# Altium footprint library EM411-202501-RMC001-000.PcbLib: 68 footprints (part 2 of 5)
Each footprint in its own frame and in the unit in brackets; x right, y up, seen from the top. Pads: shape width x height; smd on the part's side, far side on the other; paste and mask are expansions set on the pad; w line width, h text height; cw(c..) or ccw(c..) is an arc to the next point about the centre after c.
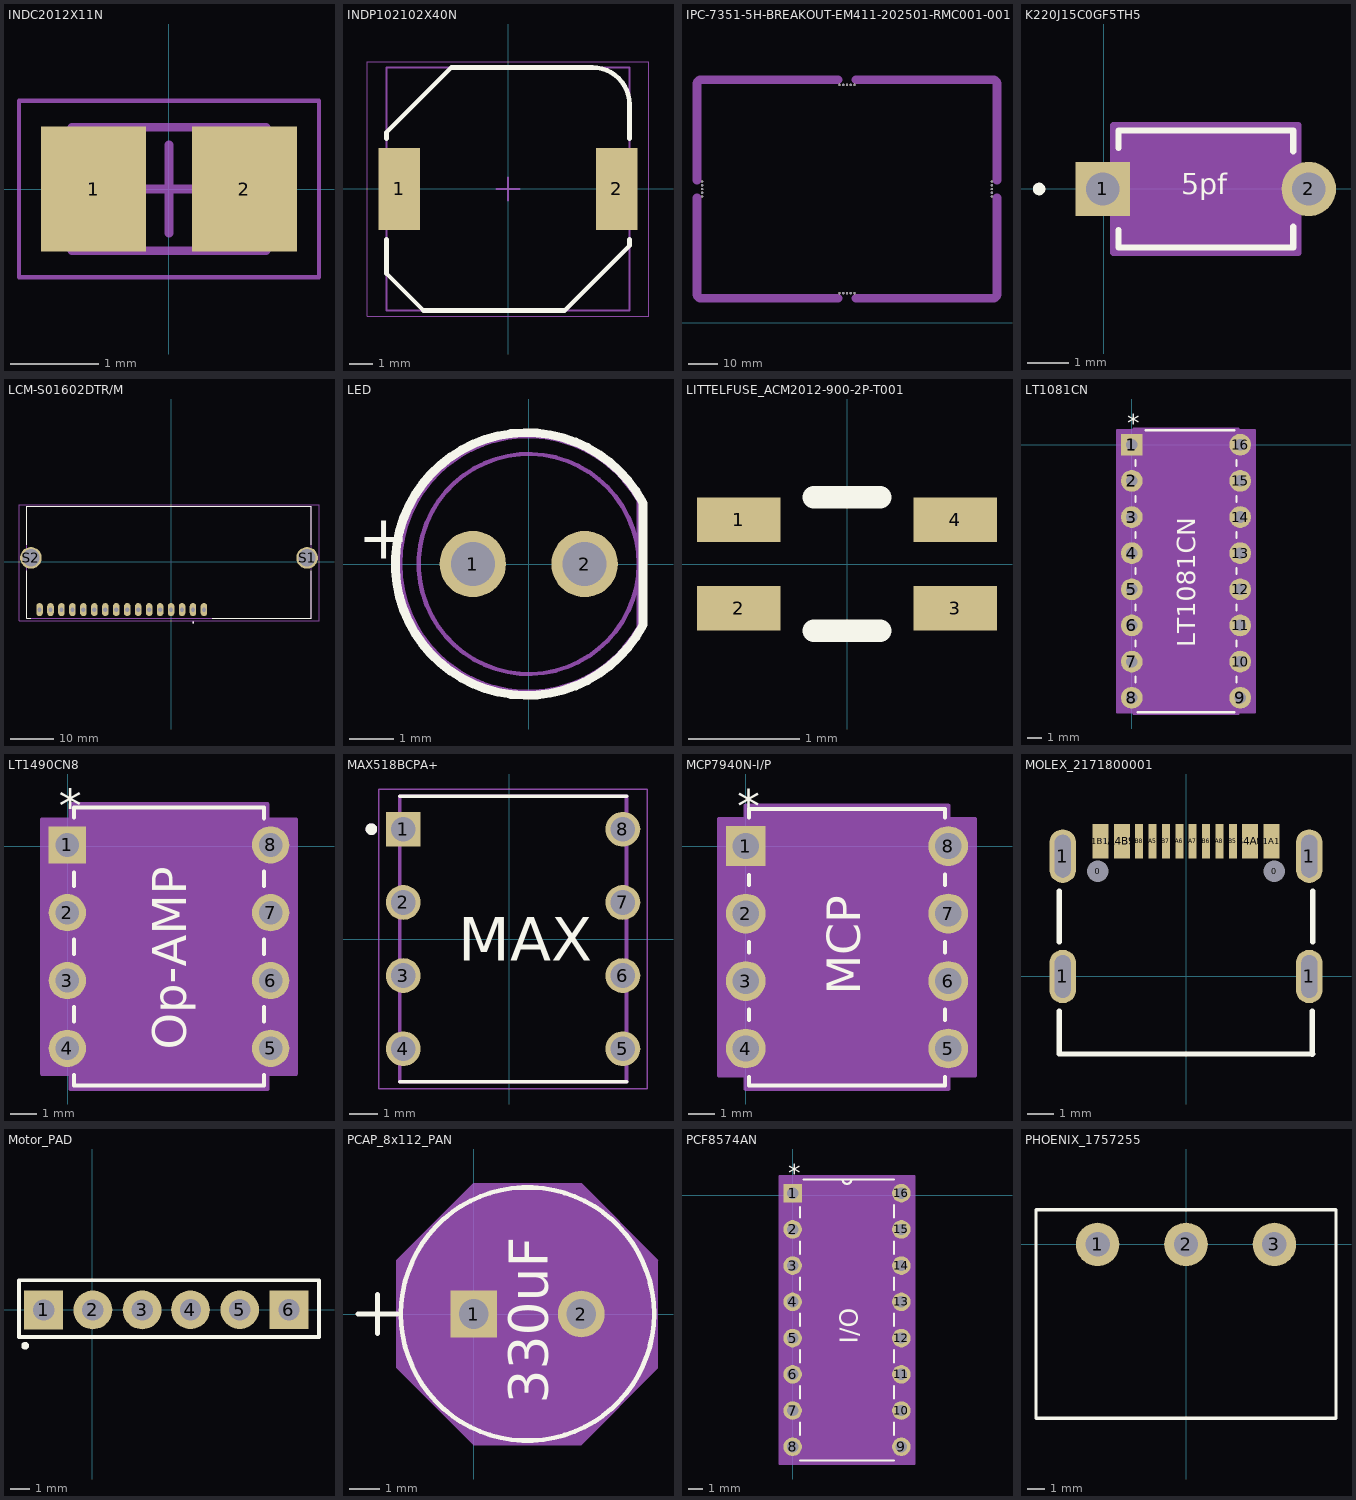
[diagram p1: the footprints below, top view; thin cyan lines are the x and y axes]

## INDC2012X11N [mm] "Chip Inductor, 2-Leads, Body 2.00x1.20mm, IPC Medium Density"
height 1.1
pads (2):
  rect 1.19x1.42 smd: 1(-0.855,0) 2(0.855,0)
Mechanical 13:
  lines w0.1: -1.1,-0.7 1.1,-0.7 1.1,0.7 -1.1,0.7 -1.1,-0.7
Mechanical 15:
  lines w0.05: -1.7,-1 1.7,-1 1.7,1 -1.7,1 -1.7,-1
  lines w0.1: -0.5,0 0.5,0 ; 0,-0.5 0,0.5
3D body "INDC2012X11N.step": height 1.1, standoff 0, extent -1.1,-0.7 1.1,0.7

## INDP102102X40N [mm] "Precision Wire Wound Inductor, 2-Leads, Body 10.20x10.15mm, IPC Medium Density"
height 4
pads (2):
  rect 1.78x3.56 smd: 1(-4.7,0) 2(4.7,0)
Top Overlay:
  lines w0.2: -5.25,-2.18 -5.25,-3.65 -3.65,-5.25 2.45,-5.25 5.25,-2.45 5.25,-2.18 ; -5.25,2.18 -5.25,2.45 -2.45,5.25 3.65,5.25 cw(c3.65,3.65) 5.25,3.65 5.25,2.18
Top Courtyard:
  lines w0.05: -6.075,-5.5 -6.075,5.5 6.075,5.5 6.075,-5.5 -6.075,-5.5
  lines w0.1: -0.5,0 0.5,0 ; 0,-0.5 0,0.5
Mechanical 13:
  lines w0.1: -5.25,-5.25 -5.25,5.25 5.25,5.25 5.25,-5.25 -5.25,-5.25
3D body "Coilcraft-MSS1038.STEP": height 3.6, standoff -0.4, extent -5.15,-5.1 5.15,5.1

## IPC-7351-5H-BREAKOUT-EM411-202501-RMC001-001 [mil] "IPC-7351 Breakout for EM411-202401-RMC001-001"
pads (20):
  round 31 hole 31 unplated: 0(403.7,1711.02) 0(403.7,1761.02) 0(403.7,1811.02) 0(403.7,1861.02) 0(403.7,1911.02) 0(2262.2,403.7) 0(2262.2,3218.35) 0(2312.2,403.7) 0(2312.2,3218.35) 0(2362.2,403.7) 0(2362.2,3218.35) 0(2412.2,403.7) 0(2412.2,3218.35) 0(2462.2,403.7) 0(2462.2,3218.35) 0(4320.71,1711.02) 0(4320.71,1761.02) 0(4320.71,1811.02) 0(4320.71,1861.02) 0(4320.71,1911.02)
Route Tool Path:
  lines w118.11: 334.64,1692.91 334.64,393.7 ccw(c393.7,393.7) 393.7,334.64 2244.09,334.65 ; 334.65,1929.13 334.65,3228.35 cw(c393.7,3228.35) 393.7,3287.4 2244.09,3287.4 ; 2480.31,334.65 4330.71,334.64 ccw(c4330.71,393.7) 4389.76,393.7 4389.76,1692.91 ; 2480.31,3287.4 4330.71,3287.4 cw(c4330.71,3228.35) 4389.76,3228.35 4389.76,1929.13

## K220J15C0GF5TH5 [mil]
pads (2):
  rect 52x52 hole 32 paste-99999 mask+0: 1(-0.55,-0.19)
  round 52 hole 32 paste-99999 mask+0: 2(196.3,-0.19)
Top Overlay:
  circle w6: c-61.55,-0.19 r3
  lines w6: 14.38,-39.29 14.38,-56.19 181.38,-56.19 181.38,-36.33 ; 14.38,38.91 14.38,55.81 181.38,55.81 181.38,35.95
  text "5pf" at 74.45,-5.19 h20
Mechanical 13:
  circle w1: c39.38,-0.19 r3
  lines w1: 19.38,-51.19 19.38,50.81 176.38,50.81 176.38,-51.19 19.38,-51.19
  text "C" at -39.62,-25.19 h50
Mechanical 15:
  region: 186.38,-61.19 9.38,-61.19 9.38,60.81 186.38,60.81
  lines w6: 9.38,-61.19 186.38,-61.19 186.38,60.81 9.38,60.81 9.38,-61.19
3D body "CAP_K-SERIES_15-H5_VIS.step": height 307.99, standoff -52.01, extent -20.96,-47.16 219.87,54.81

## LCM-S01602DTR/M [mm]
pads (18):
  oval 1.508x3.016 hole 1: 1(2.512,-11.127) 2(-0.028,-11.127) 3(-2.568,-11.127) 4(-5.108,-11.127) 5(-7.648,-11.127) 6(-10.188,-11.127) 7(-12.728,-11.127) 8(-15.268,-11.127) 9(-17.808,-11.127) 10(-20.348,-11.127) 11(-22.888,-11.127) 12(-25.428,-11.127) 13(-27.968,-11.127) 14(-30.508,-11.127) 15(7.592,-11.127) 16(5.052,-11.127)
  round 5.016 hole 4: S1(31.492,0.873) S2(-32.508,0.873)
Top Overlay:
  circle w0.2: c5.092,-14.127 r0.1
  lines w0.127: -33.508,-2.127 -33.508,-13.127 -32.508,-13.127 ; -33.508,3.873 -33.508,12.873 32.492,12.873 32.492,3.873 ; 9.492,-13.127 32.492,-13.127 32.492,-2.127
Mechanical 13:
  circle w0.2: c5.092,-14.127 r0.1
  lines w0.127: -33.508,-13.127 32.492,-13.127 32.492,12.873 -33.508,12.873 -33.508,-13.127
Mechanical 15:
  lines w0.05: -35.268,-13.647 34.252,-13.647 34.252,13.123 -35.268,13.123 -35.268,-13.647

## LED [mm]
pads (2):
  round 1.508 hole 1: 1(-1.27,0) 2(1.27,0)
Top Overlay:
  lines w0.2: 2.589,-1.401 cw(c-0.047,0) 2.589,1.401 ; 2.6,-1.38 2.6,1.38
  text "+" at -3.88,0.118 h1.02
Mechanical 13:
  circle w0.1: c0,0 r2.5
  lines w0.1: 2.493,-1.452 cw(c-0.021,0) 2.493,1.452 ; 2.5,-1.44 2.5,1.44
  text "+" at -3.887,0.131 h1.02

## LITTELFUSE_ACM2012-900-2P-T001 [mm] "Common Mode Choke"
height 1.3
pads (4):
  rect 0.75x0.4 smd: 1(-0.975,0.4) 2(-0.975,-0.4) 3(0.975,-0.4) 4(0.975,0.4)
Top Overlay:
  lines w0.2: -0.3,-0.6 0.3,-0.6 ; -0.3,0.6 0.3,0.6
3D body "acm2012-t001.step": height 1.21, standoff 0.01, extent -0.998,-0.6 0.998,0.6

## LT1081CN [mil]
pads (16):
  rect 60x60 hole 32 paste-99999 mask+0: 1(0,0)
  round 60 hole 32 paste-99999 mask+0: 2(0,-100) 3(0,-200) 4(0,-300) 5(0,-400) 6(0,-500) 7(0,-600) 8(0,-700) 9(300,-700) 10(300,-600) 11(300,-500) 12(300,-400) 13(300,-300) 14(300,-200) 15(300,-100) 16(300,0)
Top Overlay:
  lines w6: 10,-658.08 10,-641.92 ; 10,-558.08 10,-541.92 ; 10,-458.08 10,-441.92 ; 10,-358.08 10,-341.92 ; 10,-258.08 10,-241.92 ; 10,-158.08 10,-141.92 ; 10,-58.08 10,-43.1 ; 16.05,-740 283.95,-740 ; 38.46,40 283.95,40 ; 290,-658.08 290,-641.92 ; 290,-558.08 290,-541.92 ; 290,-458.08 290,-441.92 ; 290,-358.08 290,-341.92 ; 290,-258.08 290,-241.92 ; 290,-158.08 290,-141.92 ; 290,-58.08 290,-41.92
  text "LT1081CN" at 175,-560 h50
  text "*" at -12.5,35 h50
Mechanical 13:
  lines w1: 138,35 ccw(c150,35) 162,35 ; -16,-716 15,-716 15,-684 -16,-684 -16,-716 ; -16,-616 15,-616 15,-584 -16,-584 -16,-616 ; -16,-516 15,-516 15,-484 -16,-484 -16,-516 ; -16,-416 15,-416 15,-384 -16,-384 -16,-416 ; -16,-316 15,-316 15,-284 -16,-284 -16,-316 ; -16,-216 15,-216 15,-184 -16,-184 -16,-216 ; -16,-116 15,-116 15,-84 -16,-84 -16,-116 ; -16,-16 15,-16 15,16 -16,16 -16,-16 ; 15,-735 15,35 285,35 285,-735 15,-735 ; 285,-716 316,-716 316,-684 285,-684 285,-716 ; 285,-616 316,-616 316,-584 285,-584 285,-616 ; 285,-516 316,-516 316,-484 285,-484 285,-516 ; 285,-416 316,-416 316,-384 285,-384 285,-416 ; 285,-316 316,-316 316,-284 285,-284 285,-316 ; 285,-216 316,-216 316,-184 285,-184 285,-216 ; 285,-116 316,-116 316,-84 285,-84 285,-116 ; 285,-16 316,-16 316,16 285,16 285,-16
  text "*" at 12.5,-25 h50
Mechanical 15:
  region: 295,-740 340,-740 340,40 295,40 295,45 5,45 5,40 -40,40 -40,-740 5,-740 5,-745 295,-745
  lines w6: -40,-740 5,-740 5,-745 295,-745 295,-740 340,-740 340,40 295,40 295,45 5,45 5,40 -40,40 -40,-740
3D body "PDIP-16_N_LIT.step": height 140.12, standoff -100, extent -5,-735 315,35

## LT1490CN8 [mil]
pads (8):
  rect 55x55 hole 35 paste-99999 mask+0: 1(-0.56,2.06)
  round 55 hole 35 paste-99999 mask+0: 2(-0.56,-97.94) 3(-0.56,-197.94) 4(-0.56,-297.94) 5(299.44,-297.94) 6(299.44,-197.94) 7(299.44,-97.94) 8(299.44,2.06)
Top Overlay:
  lines w6: 9.44,-337.29 9.44,-352.94 289.44,-352.94 289.44,-337.29 ; 9.44,-258.59 9.44,-237.29 ; 9.44,-158.59 9.44,-137.29 ; 9.44,-58.59 9.44,-38.54 ; 9.44,42.66 9.44,57.06 289.44,57.06 289.44,41.41 ; 289.44,-258.59 289.44,-237.29 ; 289.44,-158.59 289.44,-137.29 ; 289.44,-58.59 289.44,-37.29
  text "Op-AMP" at 175,-300 h50
  text "*" at -13.06,34.56 h50
Mechanical 13:
  lines w1: 137.44,52.06 ccw(c149.44,52.06) 161.44,52.06 ; -18.06,-315.44 14.44,-315.44 14.44,-280.44 -18.06,-280.44 -18.06,-315.44 ; -18.06,-215.44 14.44,-215.44 14.44,-180.44 -18.06,-180.44 -18.06,-215.44 ; -18.06,-115.44 14.44,-115.44 14.44,-80.44 -18.06,-80.44 -18.06,-115.44 ; -18.06,-15.44 14.44,-15.44 14.44,19.56 -18.06,19.56 -18.06,-15.44 ; 14.44,-347.94 14.44,52.06 284.44,52.06 284.44,-347.94 14.44,-347.94 ; 284.44,-315.44 316.94,-315.44 316.94,-280.44 284.44,-280.44 284.44,-315.44 ; 284.44,-215.44 316.94,-215.44 316.94,-180.44 284.44,-180.44 284.44,-215.44 ; 284.44,-115.44 316.94,-115.44 316.94,-80.44 284.44,-80.44 284.44,-115.44 ; 284.44,-15.44 316.94,-15.44 316.94,19.56 284.44,19.56 284.44,-15.44
  text "*" at 11.94,-22.94 h50
Mechanical 15:
  region: 294.44,-335.44 336.94,-335.44 336.94,39.56 294.44,39.56 294.44,62.06 4.44,62.06 4.44,39.56 -38.06,39.56 -38.06,-335.44 4.44,-335.44 4.44,-357.94 294.44,-357.94
  lines w6: -38.06,-335.44 4.44,-335.44 4.44,-357.94 294.44,-357.94 294.44,-335.44 336.94,-335.44 336.94,39.56 294.44,39.56 294.44,62.06 4.44,62.06 4.44,39.56 -38.06,39.56 -38.06,-335.44
3D body "PDIP-8_N_LIT.step": height 160.12, standoff -100, extent -5,-350 315,50

## MAX518BCPA+ [mm]
pads (8):
  rect 1.21x1.21 / inner round 1.21 / far side rect 1.21x1.21 hole 0.86: 1(-3.683,3.81)
  round 1.21 hole 0.86: 2(-3.683,1.27) 3(-3.683,-1.27) 4(-3.683,-3.81) 5(3.937,-3.81) 6(3.937,-1.27) 7(3.937,1.27) 8(3.937,3.81)
Top Overlay:
  circle w0.2: c-4.788,3.81 r0.1
  lines w0.127: -3.808,-4.955 4.062,-4.955 ; -3.808,4.955 4.062,4.955
  text "MAX" at -1.778,-0.762 h1.52
Mechanical 13:
  circle w0.2: c-4.788,3.81 r0.1
  lines w0.127: -3.808,-4.955 4.062,-4.955 4.062,4.955 -3.808,4.955 -3.808,-4.955
Mechanical 15:
  lines w0.05: -4.538,-5.205 4.792,-5.205 4.792,5.205 -4.538,5.205 -4.538,-5.205

## MCP7940N-I/P [mil]
pads (8):
  rect 59x59 hole 39 paste-99999 mask+0: 1(0,0)
  round 59 hole 39 paste-99999 mask+0: 2(0,-100) 3(0,-200) 4(0,-300) 5(300,-300) 6(300,-200) 7(300,-100) 8(300,0)
Top Overlay:
  lines w6: 5,-342.31 5,-355 295,-355 295,-342.31 ; 5,-257.69 5,-242.31 ; 5,-157.69 5,-142.31 ; 5,-57.69 5,-42.6 ; 5,42.6 5,55 295,55 295,42.31 ; 295,-257.69 295,-242.31 ; 295,-157.69 295,-142.31 ; 295,-57.69 295,-42.31
  text "*" at -12.5,34.5 h50
  text "MCP" at 170,-220 h50
Mechanical 13:
  lines w1: -19.5,-319.5 -19.5,-280.5 10,-280.5 10,-319.5 -19.5,-319.5 ; -19.5,-219.5 -19.5,-180.5 10,-180.5 10,-219.5 -19.5,-219.5 ; -19.5,-119.5 -19.5,-80.5 10,-80.5 10,-119.5 -19.5,-119.5 ; -19.5,-19.5 -19.5,19.5 10,19.5 10,-19.5 -19.5,-19.5 ; 10,-350 290,-350 290,50 10,50 10,-350 ; 290,-319.5 290,-280.5 319.5,-280.5 319.5,-319.5 290,-319.5 ; 290,-219.5 290,-180.5 319.5,-180.5 319.5,-219.5 290,-219.5 ; 290,-119.5 290,-80.5 319.5,-80.5 319.5,-119.5 290,-119.5 ; 290,-19.5 290,19.5 319.5,19.5 319.5,-19.5 290,-19.5
  text "*" at 7.5,-25 h50
Mechanical 15:
  region: 300,-340 339.5,-340 339.5,40 300,40 300,60 0,60 0,40 -39.5,40 -39.5,-340 0,-340 0,-360 300,-360
  lines w6: -39.5,-340 -39.5,40 0,40 0,60 300,60 300,40 339.5,40 339.5,-340 300,-340 300,-360 0,-360 0,-340 -39.5,-340
3D body "PDIP8_300MC_MCH.step": height 215.12, standoff -100, extent -5,-350 315,50

## MOLEX_2171800001 [mm]
height 7.4
pads (18):
  round 0.4 hole 0.8 unplated: 0(-3.3,3.94) 0(3.3,3.94)
  oval 1x2 hole 0.6 slot 1.6 at 90 deg: 1(-4.61,0) 1(-4.61,4.5) 1(4.61,0) 1(4.61,4.5)
  rect 0.6x1.3 smd: A1B12(-3.2,5.06) A4B9(-2.4,5.06) B1A12(3.2,5.06) B4A9(2.4,5.06)
  rect 0.3x1.3 smd: A5(-1.25,5.06) A6(-0.25,5.06) A7(0.25,5.06) A8(1.25,5.06) B5(1.75,5.06) B6(0.75,5.06) B7(-0.75,5.06) B8(-1.75,5.06)
Top Overlay:
  lines w0.2: -4.735,-1.3 -4.735,-2.9 4.735,-2.9 ; -4.735,1.3 -4.735,3.2 ; 4.723,-2.905 4.723,-1.305 ; 4.735,1.3 4.735,3.2
3D body "2171800001.stp": height 7.79, standoff -1.29, extent -4.73,-2.902 4.74,5.498

## Motor_PAD [mm]
pads (6):
  rect 2x2 hole 1.1: 1(-2.519,-0.005) 6(10.136,0.006)
  round 2 hole 1.1: 2(0.021,-0.005) 3(2.561,-0.005) 4(5.056,0.006) 5(7.596,0.006)
Top Overlay:
  circle w0.2: c-3.47,-1.851 r0.1
  lines w0.2: -3.789,-1.405 -3.789,1.524 11.684,1.524 11.684,-1.405 -3.789,-1.405
3D body "TSW-103-07-G-S.stp": height 8.41, standoff -2.51, extent -3.916,-1.275 3.831,1.265
3D body "TSW-103-07-G-S.stp": height 8.41, standoff -2.51, extent 3.786,-1.264 11.533,1.276

## PCAP_8x112_PAN [mil]
pads (2):
  rect 60x60 hole 38 paste-99999 mask+0: 1(0,0)
  round 60 hole 38 paste-99999 mask+0: 2(138,0)
Top Overlay:
  circle w6: c69,0 r162.5
  lines w6: -148.5,0 -98.5,0 ; -123.5,-25 -123.5,25
  text "330uF" at 95,-115 h50
Mechanical 13:
  circle w1: c69,0 r157.5
  lines w1: -148.5,0 -98.5,0 ; -123.5,-25 -123.5,25
Mechanical 15:
  region: -98.5,68.97 0,167.5 137.97,167.5 236.5,68.97 236.5,-68.97 137.97,-167.5 0,-167.5 -98.5,-68.97
  lines w1: -98.5,-68.97 -98.5,68.97 0,167.5 137.97,167.5 236.5,68.97 236.5,-68.97 137.97,-167.5 0,-167.5 -98.5,-68.97
3D body "PCAP_8x112_PAN.step": height 453.62, standoff -184.02, extent -88.5,-157.5 227.57,157.5

## PCF8574AN [mil]
pads (16):
  rect 51x51 / inner round 60 / far side rect 51x51 hole 31 paste-99999 mask-25.5: 1(-0.87,5.18)
  round 51 / inner round 60 / far side round 51 hole 31 paste-99999 mask-25.5: 2(-0.87,-94.82) 3(-0.87,-194.82) 4(-0.87,-294.82) 5(-0.87,-394.82) 6(-0.87,-494.82) 7(-0.87,-594.82) 8(-0.87,-694.82) 9(299.13,-694.82) 10(299.13,-594.82) 11(299.13,-494.82) 12(299.13,-394.82) 13(299.13,-294.82) 14(299.13,-194.82) 15(299.13,-94.82) 16(299.13,5.18)
Top Overlay:
  lines w6: 19.13,-732.32 279.13,-732.32 ; 19.13,-661.8 19.13,-627.83 ; 19.13,-561.8 19.13,-527.83 ; 19.13,-461.8 19.13,-427.83 ; 19.13,-361.8 19.13,-327.83 ; 19.13,-261.8 19.13,-227.83 ; 19.13,-161.8 19.13,-127.83 ; 19.13,-61.8 19.13,-33.42 ; 29.88,42.68 279.13,42.68 ; 137.13,42.68 ccw(c149.13,42.68) 161.13,42.68 ; 279.13,-661.8 279.13,-627.83 ; 279.13,-561.8 279.13,-527.83 ; 279.13,-461.8 279.13,-427.83 ; 279.13,-361.8 279.13,-327.83 ; 279.13,-261.8 279.13,-227.83 ; 279.13,-161.8 279.13,-127.83 ; 279.13,-61.8 279.13,-27.83
  text "I/O" at 179.13,-409.82 h50
  text "*" at -13.37,35.68 h50
Mechanical 13:
  lines w0: 137.13,42.68 ccw(c149.13,42.68) 161.13,42.68
  lines w1: -16.37,-710.32 19.13,-710.32 19.13,-679.32 -16.37,-679.32 -16.37,-710.32 ; -16.37,-610.32 19.13,-610.32 19.13,-579.32 -16.37,-579.32 -16.37,-610.32 ; -16.37,-510.32 19.13,-510.32 19.13,-479.32 -16.37,-479.32 -16.37,-510.32 ; -16.37,-410.32 19.13,-410.32 19.13,-379.32 -16.37,-379.32 -16.37,-410.32 ; -16.37,-310.32 19.13,-310.32 19.13,-279.32 -16.37,-279.32 -16.37,-310.32 ; -16.37,-210.32 19.13,-210.32 19.13,-179.32 -16.37,-179.32 -16.37,-210.32 ; -16.37,-110.32 19.13,-110.32 19.13,-79.32 -16.37,-79.32 -16.37,-110.32 ; -16.37,-10.32 19.13,-10.32 19.13,20.68 -16.37,20.68 -16.37,-10.32 ; 19.13,-732.32 19.13,42.68 279.13,42.68 279.13,-732.32 19.13,-732.32 ; 279.13,-710.32 314.63,-710.32 314.63,-679.32 279.13,-679.32 279.13,-710.32 ; 279.13,-610.32 314.63,-610.32 314.63,-579.32 279.13,-579.32 279.13,-610.32 ; 279.13,-510.32 314.63,-510.32 314.63,-479.32 279.13,-479.32 279.13,-510.32 ; 279.13,-410.32 314.63,-410.32 314.63,-379.32 279.13,-379.32 279.13,-410.32 ; 279.13,-310.32 314.63,-310.32 314.63,-279.32 279.13,-279.32 279.13,-310.32 ; 279.13,-210.32 314.63,-210.32 314.63,-179.32 279.13,-179.32 279.13,-210.32 ; 279.13,-110.32 314.63,-110.32 314.63,-79.32 279.13,-79.32 279.13,-110.32 ; 279.13,-10.32 314.63,-10.32 314.63,20.68 279.13,20.68 279.13,-10.32
  text "*" at -13.37,35.68 h50
Mechanical 15:
  region: 334.63,-742.32 -36.37,-742.32 -36.37,52.68 334.63,52.68
  lines w6: -36.37,-742.32 -36.37,52.68 334.63,52.68 334.63,-742.32 -36.37,-742.32
3D body "N16.step": height 205.12, standoff -100, extent -10.87,-722.3 309.13,52.66

## PHOENIX_1757255 [mm] "PCB header - MSTBA 2,5/ 3-G-5,08"
height 8.57
pads (3):
  round 2.5 hole 1.4: 1(-5.08,0) 2(0,0) 3(5.08,0)
Top Overlay:
  lines w0.2: -8.62,-10 8.62,-10 8.62,2 -8.62,2 -8.62,-10
3D body "1757255.stp": height 8.6, standoff -3.5, extent -8.62,-10.002 8.62,2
